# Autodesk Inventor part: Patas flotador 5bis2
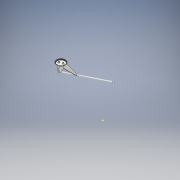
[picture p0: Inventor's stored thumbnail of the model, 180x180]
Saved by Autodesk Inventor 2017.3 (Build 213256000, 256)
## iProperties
Part Number: Patas flotador 5bis2
Material: Plástico ABS
Document SubType Name: Modeling
Designer: PABLO HERNANDEZ
Density: 1.06 g/cm^3
Appearance: Suave - Blanco
Mass: 4.28877 g
Surface Area: 39.5254 cm^2
Volume: 4.04601 cm^3
Author: M.RICO
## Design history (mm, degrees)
sketch "Boceto1"
  geometry: C1 r 16 at (0, 0); 1 further point
  constraints: 1 centre point, 1 coincident
  dimensions: "d0" = 32 diameter of C1
extrude "Extrusión1" new body sketch "Boceto1" distance "d1" = 1; taper "d2" = 0 deg; dims "d93" = 1, "d94" = 0
sketch "Boceto2"
  geometry: C1 r 16 at (0, 0); C2 r 15 at (0, 0); C3 r 14 at (0, 0); 1 further point
  constraints: 3 centre point, 1 coincident
  dimensions: "d3" = 1 radial gap between concentric circles of C1 C2; "d4" = 1 radial gap between concentric circles of C2 C3
extrude "Extrusión2" join sketch "Boceto2" distance "d5" = 3; taper "d6" = 0 deg
sketch "Boceto3"
  geometry: C1 r 15 at (0, 0); C2 r 14 at (0, 0); 1 further point
  constraints: 2 centre point, 1 coincident
  dimensions: "d7" = 1 radial gap between concentric circles of C1 C2; "d123" = 30 diameter of C1
extrude "Extrusión3" join sketch "Boceto3" distance "d8" = 2; taper "d9" = 0 deg
sketch "Boceto4"
  geometry: C1 r 16 at (0, 0); 1 further point
  constraints: 1 centre point, 1 coincident
extrude "Extrusión4" cut sketch "Boceto4" distance "d10" = 0.5; taper "d11" = 0 deg
sketch "Boceto7"
  geometry: L1 (1.5, -15.93)-(1.5, 15.93); L2 (-1.5, -15.93)-(-1.5, 15.93); A1 r 16 centre (0, 0) between (1.5, 15.93) and (-1.5, 15.93); A2 r 16 centre (0, 0) between (-1.5, -15.93) and (1.5, -15.93); 2 further points
  constraints: 4 end point, 4 point on circle, 2 centre point, 1 coincident
extrude "Extrusión7" join sketch "Boceto7" distance "d63" = 25; taper "d64" = 0 deg
fillet "Empalme2" dims "d95" = 3
fillet "Empalme3" dims "d96" = 0.5
sketch "Boceto13"
  geometry: C1 r 1.2 at (-6, 0) reference; C2 r 1.75 at (-6, 0); C3 r 1.2 at (6, 0) reference; C4 r 1.75 at (6, 0); 1 further point
  constraints: 2 centre point, 2 coincident
  dimensions: "d118" = 3.5 diameter of C2; "d119" = 3.5 diameter of C4
extrude "Extrusión10" join sketch "Boceto13" distance "d120" = 3; taper "d121" = 0 deg
fillet "Empalme4" dims "d122" = 1
sketch "Boceto14"
  geometry: 1 further point
sketch "Boceto15"
  geometry: C1 r 1.2 at (6, 0) reference; C2 r 2.5 at (6, 0); C3 r 1.2 at (-6, 0) reference; C4 r 2.5 at (-6, 0); 1 further point
  constraints: 2 centre point, 2 coincident
  dimensions: "d124" = 5 diameter of C2; "d125" = 5 diameter of C4
extrude "Extrusión11" cut sketch "Boceto15" distance "d126" = 10; taper "d127" = 0 deg
hole "Agujero7" diameter "d151" = 2.4; stored, may be unused: countersink angle "d155" = 90 deg, drill point angle "d157" = 118 deg; dims "d149" = 10, "d150" = 10, "d152" = 6, "d153" = 4, "d154" = 2, "d156" = 8
hole "Agujero8" diameter "d160" = 2.4; stored, may be unused: countersink angle "d164" = 90 deg, drill point angle "d166" = 118 deg; dims "d158" = 10, "d159" = 10, "d161" = 6, "d162" = 4, "d163" = 2, "d165" = 8
node "Eje de trabajo1"
feature "Desplazar cuerpo1"
feature "Compuesta1"
feature "Desplazar cuerpo2"
node "Eje de trabajo2"
feature "Desplazar cuerpo3"
node "Plano de trabajo6"
sketch "Boceto27"
  geometry: L1 (0, 0)-(-149.324, -102.291); L2 (-134.431, -229.557)-(132.044, -87.232); L3 (-65.839, 96.112)-(-215.163, -6.179); L4 (-53.123, 77.549)-(-202.447, -24.742); L5 (-53.123, 77.549)-(-215.163, -6.179); C1 r 14 at (-149.324, -102.291) reference
  constraints: 10 end point, 2 parallel
  dimensions: "d191" = 116.5 distance between parallel lines of L1 L3; "d192" = 94 distance between parallel lines of L1 L4
node "Plano de trabajo7"
node "Plano de trabajo8"
sketch "Boceto28"
  geometry: C1 r 2 at (0, 0); 1 further point
  constraints: 1 centre point
  dimensions: "d177" = 4 diameter of C1
extrude "Extrusión14" join sketch "Boceto28" stored distance "d178" = 10; taper "d179" = 0 deg
sketch "Boceto29"
  geometry: L1 (-0.28, 0)-(0, 0) reference; L2 (0, 0)-(-102.216, -91.987); L3 (-0.28, 23.165)-(-0.28, 0) reference; L4 (0, 23.165)-(0, 0) reference; L5 (0, 0)-(0, 23.165); L6 (0, 23.165)-(-105.015, -89.134); C1 r 2 at (-103.554, -90.5) reference; A1 r 2 centre (-103.554, -90.5) between (-102.216, -91.987) and (-105.015, -89.134) reference; 1 further point
  constraints: 6 end point, 2 point on circle, 2 tangent, 1 collinear
extrude "Extrusión15" join sketch "Boceto29" stored distance "d180" = 10; taper "d181" = 0 deg
node "Plano de trabajo9"
sketch "Boceto30"
  geometry: L1 (1.356, 23.165)-(1.356, 0) reference; L2 (1.356, 0)-(-130.469, -92.139); L3 (1.356, 0)-(1.356, 23.165); L4 (1.356, 23.165)-(-132.897, -88.965); A1 r 2 centre (-131.615, -90.5) between (-130.469, -92.139) and (-132.897, -88.965) reference; A2 r 2 centre (-131.615, -90.5) between (-132.897, -88.965) and (-130.469, -92.139); 1 further point
  constraints: 6 end point, 4 point on circle, 2 tangent, 1 centre point, 1 coincident, 1 vertical
extrude "Extrusión16" join sketch "Boceto30" distance "d182" = 3; taper "d183" = 0 deg
node "Plano de trabajo11"
sketch "Boceto31"
  geometry: L1 (-3.903, -5.958)-(206.564, -5.958); L2 (206.564, -5.958)-(206.564, 135.04); L3 (206.564, 135.04)-(-3.903, 135.04); L4 (-3.903, 135.04)-(-3.903, -5.958); 1 further point
  constraints: 8 end point, 2 parallel, 1 horizontal, 1 perpendicular
extrude "Extrusión17" cut sketch "Boceto31" distance "d186" = 200; taper "d187" = 0 deg
sketch "Boceto32"
  geometry: C1 r 2 at (0, 0) reference; C2 r 1 at (0, 0); 1 further point
  constraints: 1 centre point
  dimensions: "d188" = 1 radial gap between concentric circles of C1 C2
extrude "Extrusión18" cut sketch "Boceto32" distance "d189" = 6; taper "d190" = 0 deg
node "Plano de trabajo12"
mirror "Simetría1"
fillet "Empalme5" dims "d194" = 14
node "Sólido1"
node "Sup1"
other parameters: "sa_0" = 4, "d167" = 90 deg, "d168" = -149.324, "d169" = -102.291, "d170" = 0, "d171" = 9.86699, "d185" = 153, "d193" = 90 deg
